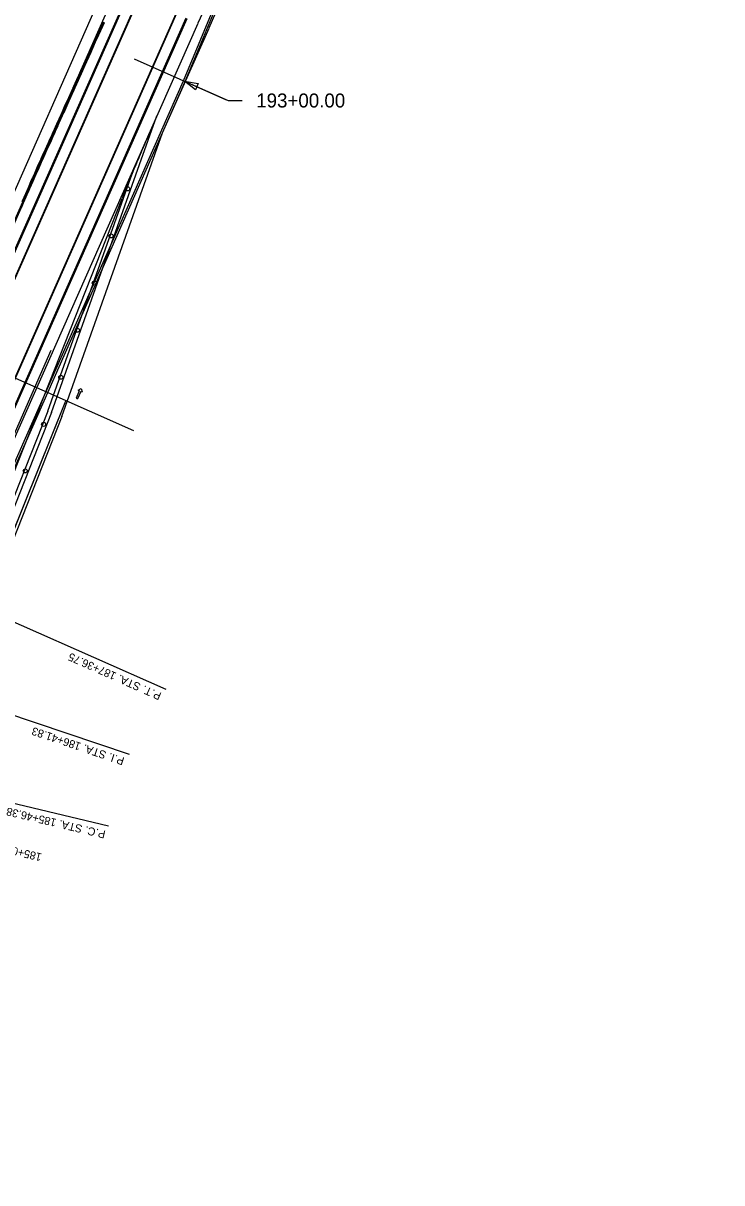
# Model space of a CAD drawing. Extents: x 659657 to 668193, y 633084 to 648639.
# Drawn here: x 662768 to 663466, y 643023 to 644182 of the extents above; entities that cross this region are included whole.
import ezdxf

# ---------------------------------------------------------------- set-up
doc = ezdxf.new("R2010")
doc.units = 0
for name, color, linetype in [('R_Border Prem', 7, 'Continuous'), ('R_MOT_Stage 1A_Striping', 7, 'Continuous'), ('R_MOT_Stage 1B', 7, 'Continuous'), ('R_MOT_Stage 1B_Striping', 7, 'Continuous'), ('R_MOT_Stage 1C', 7, 'Continuous'), ('R_MOT_Stage 1C_Striping', 7, 'Continuous'), ('R_MOT_Stage 1C_Striping_PPM', 7, 'Continuous'), ('R_MOT_Stage 2', 7, 'Continuous'), ('R_MOT_Stage 2_Striping', 7, 'Continuous'), ('R_MOT_Stage 2_Striping_PPM', 7, 'Continuous'), ('R_MOT_Stage 3', 7, 'Continuous'), ('R_MOT_Stage 3_Striping', 7, 'Continuous'), ('R_MOT_Stage 3_Striping_PPM', 7, 'Continuous'), ('R_MOT_Stage 4_Striping', 7, 'Continuous'), ('R_MOT_Stage 4_Striping_PPM', 7, 'Continuous'), ('R_MOT_Stage 5_Striping_PPM', 7, 'Continuous'), ('T_SIGNAL CONTROL CABINET', 7, 'Continuous')]:
    doc.layers.add(name, color=color, linetype=linetype)

msp = doc.modelspace()

# ---------------------------------------------------------------- linework, layer by layer
at = {"layer": 'R_Border Prem'}
msp.add_line((661686.8, 641562.9), (662861.9, 644217.7), dxfattribs=at)
at = {"layer": 'R_MOT_Stage 1A_Striping'}
for points in [[(662693, 643612.5), (662910.2, 643516.4)], [(662654.4, 643525.2), (662873.4, 643451.4)], [(662632.3, 643432.4), (662852.8, 643379.8)]]:
    msp.add_lwpolyline(points, dxfattribs=at)
at = {"layer": 'R_MOT_Stage 1B'}
for p, q in [((662927.9, 644124.5), (663042.2, 644399.9)), ((662929.7, 644123.8), (663044, 644399.2)), ((662731.8, 643681.5), (662927.9, 644124.5)), ((662733.6, 643680.7), (662929.7, 644123.7))]:
    msp.add_line(p, q, dxfattribs=at)
at = {"layer": 'R_MOT_Stage 1B_Striping'}
for p, q in [((662927.9, 644124.5), (663042.2, 644399.9)), ((662653.9, 643589.7), (662920.4, 644191.8)), ((662664, 643585.2), (662930.5, 644187.3)), ((662731.8, 643681.5), (662927.9, 644124.5)), ((662675.3, 643583.6), (662795.5, 643855.1))]:
    msp.add_line(p, q, dxfattribs=at)
for points in [[(662693, 643612.5), (662910.2, 643516.4)], [(662654.4, 643525.2), (662873.4, 643451.4)], [(662632.3, 643432.4), (662852.8, 643379.8)]]:
    msp.add_lwpolyline(points, dxfattribs=at)
at = {"layer": 'R_MOT_Stage 1C'}
for centre in [(662872.2, 644016.5), (662855.5, 643969.4), (662838.7, 643922.3), (662821.9, 643875.2), (662805.2, 643828.1), (662788, 643781.1), (662769.6, 643734.6)]:
    msp.add_circle(centre, 2, dxfattribs=at)
at = {"layer": 'R_MOT_Stage 1C_Striping'}
for p, q in [((662884, 644040.7), (662901.3, 644089.3)), ((662795.9, 643793), (662884, 644040.7)), ((662795.9, 643793), (662675.6, 643489.1))]:
    msp.add_line(p, q, dxfattribs=at)
at = {"layer": 'R_MOT_Stage 1C_Striping_PPM'}
for p, q in [((662883.3, 644106.6), (662920.9, 644191.6)), ((662893.8, 644101.9), (662931.4, 644186.9)), ((662896.1, 644077.4), (662942.4, 644182)), ((662907, 644072.6), (662953.4, 644177.2)), ((662859, 644051.7), (662883.3, 644106.6)), ((662869.5, 644047.1), (662893.8, 644101.9)), ((662716.3, 643671.4), (662896.1, 644077.4)), ((662806.2, 643789.1), (662907, 644072.6)), ((662694.8, 643680.9), (662859, 644051.7)), ((662705.4, 643676.2), (662869.5, 644047.1)), ((662806.2, 643789.1), (662685.9, 643485.2))]:
    msp.add_line(p, q, dxfattribs=at)
for radius in [5685.6, 5673.6]:
    msp.add_arc((668141.4, 641880.7), radius, 145.4889, 156.1234, dxfattribs=at)
at = {"layer": 'R_MOT_Stage 2'}
for centre in [(662872.2, 644016.5), (662855.5, 643969.4), (662838.7, 643922.3), (662821.9, 643875.2), (662805.2, 643828.1), (662788, 643781.1), (662769.6, 643734.6)]:
    msp.add_circle(centre, 2, dxfattribs=at)
at = {"layer": 'R_MOT_Stage 2_Striping'}
for p, q in [((662884, 644040.7), (662901.3, 644089.3)), ((662795.9, 643793), (662884, 644040.7)), ((662795.9, 643793), (662675.6, 643489.1))]:
    msp.add_line(p, q, dxfattribs=at)
at = {"layer": 'R_MOT_Stage 2_Striping_PPM'}
for p, q in [((662920.9, 644191.6), (662694.8, 643680.9)), ((662705.4, 643676.2), (662931.4, 644186.9)), ((662896.1, 644077.4), (662942.4, 644182)), ((662907, 644072.6), (662953.4, 644177.2)), ((662716.3, 643671.4), (662896.1, 644077.4)), ((662806.2, 643789.1), (662907, 644072.6)), ((662806.2, 643789.1), (662685.9, 643485.2))]:
    msp.add_line(p, q, dxfattribs=at)
for radius in [5685.6, 5673.6]:
    msp.add_arc((668141.4, 641880.7), radius, 145.4889, 156.1234, dxfattribs=at)
at = {"layer": 'R_MOT_Stage 3'}
for points in [[(662765.8, 643997.5), (662768, 644002.6), (662771.6, 644010.7), (662772.9, 644013.6), (662774.3, 644016.8), (662777.6, 644024.2), (662778.6, 644026.6), (662778.9, 644027.2), (662780, 644029.7), (662780.6, 644031.1), (662783.5, 644037.6), (662787, 644045.4), (662787.1, 644045.8), (662789.5, 644051), (662791.3, 644055.1), (662793.6, 644060.2), (662794.4, 644061.8), (662795.8, 644064.9), (662797.2, 644068.1), (662799.1, 644072.2), (662800.3, 644075), (662802.1, 644078.9), (662802.5, 644079.7), (662802.7, 644080.3), (662807, 644089.7), (662808.2, 644092.5), (662808.4, 644092.8), (662810.5, 644097.6), (662813.6, 644104.5), (662813.7, 644104.7), (662814.6, 644106.8), (662818.6, 644115.6), (662819.2, 644116.9), (662819.6, 644117.8), (662819.7, 644118.1), (662824, 644127.7), (662825.2, 644130.3), (662825.8, 644131.7), (662826.6, 644133.5), (662831.2, 644143.7), (662833.4, 644148.7), (662833.4, 644148.7), (662834.4, 644150.9), (662837.2, 644157.1), (662840, 644163.4), (662841, 644165.7), (662842.1, 644168.2), (662843.2, 644170.5), (662843.4, 644171), (662848.8, 644182.9)], [(662847, 644183.7), (662841.6, 644171.8), (662841.4, 644171.3), (662840.3, 644169), (662839.2, 644166.5), (662838.2, 644164.2), (662835.4, 644157.9), (662832.6, 644151.7), (662831.6, 644149.5), (662831.6, 644149.5), (662829.4, 644144.5), (662824.8, 644134.3), (662824, 644132.5), (662823.4, 644131.1), (662822.2, 644128.5), (662817.9, 644118.9), (662817.8, 644118.6), (662817.3, 644117.7), (662816.8, 644116.4), (662812.8, 644107.6), (662811.9, 644105.5), (662811.8, 644105.4), (662808.7, 644098.5), (662806.5, 644093.6), (662806.4, 644093.3), (662805.1, 644090.6), (662800.9, 644081.1), (662800.6, 644080.5), (662800.2, 644079.7), (662798.5, 644075.8), (662797.2, 644073), (662795.4, 644068.9), (662794, 644065.8), (662792.5, 644062.6), (662791.8, 644061), (662789.5, 644055.9), (662787.7, 644051.8), (662785.3, 644046.6), (662785.1, 644046.2), (662781.7, 644038.4), (662778.8, 644031.9), (662778.2, 644030.5), (662777.1, 644028), (662776.8, 644027.4), (662775.7, 644025), (662772.5, 644017.6), (662771.1, 644014.4), (662769.8, 644011.5), (662766.2, 644003.4)]]:
    msp.add_lwpolyline(points, dxfattribs=at)
at = {"layer": 'R_MOT_Stage 3_Striping'}
for p, q in [((662566.8, 643518.9), (662873.8, 644212.4)), ((662566.8, 643518.9), (662873.8, 644212.4)), ((662576.9, 643514.4), (662883.9, 644208)), ((662576.9, 643514.4), (662883.9, 644208)), ((662792.1, 643794.4), (662876.9, 644032.5)), ((662792.1, 643794.4), (662622.7, 643366.2))]:
    msp.add_line(p, q, dxfattribs=at)
msp.add_lwpolyline([(662664.5, 643771.8), (662673, 643789.3), (662681.2, 643807.2), (662686.7, 643819.5), (662692.2, 643831.8), (662703.2, 643856.3), (662714.5, 643881.9), (662720.2, 643894.8), (662725.9, 643907.6), (662736.5, 643931.3), (662742.3, 643944.5), (662748.1, 643957.7), (662754.9, 643973), (662761.7, 643988.3), (662787, 644045.4), (662800.3, 644075), (662807, 644089.7), (662813.6, 644104.5), (662825.8, 644131.7), (662841, 644165.7), (662848.8, 644183.1)], dxfattribs=at)
msp.add_arc((664648, 643302), 1915.9, 156.1234, 157.5861, dxfattribs=at)
at = {"layer": 'R_MOT_Stage 3_Striping_PPM'}
for p, q in [((662920.9, 644191.6), (662694.8, 643680.9)), ((662705.4, 643676.2), (662931.4, 644186.9)), ((662896.1, 644077.4), (662942.4, 644182)), ((662907, 644072.6), (662953.4, 644177.2)), ((662716.3, 643671.4), (662896.1, 644077.4)), ((662806.2, 643789.1), (662907, 644072.6)), ((662806.2, 643789.1), (662685.9, 643485.2))]:
    msp.add_line(p, q, dxfattribs=at)
for radius in [5685.6, 5673.6]:
    msp.add_arc((668141.4, 641880.7), radius, 145.4889, 156.1234, dxfattribs=at)
at = {"layer": 'R_MOT_Stage 4_Striping'}
for q in [(662876.9, 644032.5), (662622.7, 643366.2)]:
    msp.add_line((662792.1, 643794.4), q, dxfattribs=at)
at = {"layer": 'R_MOT_Stage 4_Striping_PPM'}
for p, q in [((662703.1, 643888.6), (662850.9, 644222.5)), ((662716.8, 643889.9), (662861.9, 644217.7)), ((662727.8, 643885), (662872.9, 644212.8)), ((662738.3, 643880.4), (662883.4, 644208.2)), ((662920.9, 644191.6), (662694.8, 643680.9)), ((662705.4, 643676.2), (662931.4, 644186.9)), ((662896.1, 644077.4), (662942.4, 644182)), ((662907, 644072.6), (662953.4, 644177.2)), ((662716.3, 643671.4), (662896.1, 644077.4)), ((662806.2, 643789.1), (662907, 644072.6)), ((662806.2, 643789.1), (662685.9, 643485.2))]:
    msp.add_line(p, q, dxfattribs=at)
msp.add_arc((668141.4, 641880.7), 5673.6, 145.4889, 156.1234, dxfattribs=at)
at = {"layer": 'R_MOT_Stage 5_Striping_PPM'}
for p, q in [((662703.1, 643888.6), (662850.9, 644222.5)), ((662716.8, 643889.9), (662861.9, 644217.7)), ((662727.8, 643885), (662872.9, 644212.8)), ((662738.3, 643880.4), (662883.4, 644208.2)), ((662920.9, 644191.6), (662694.8, 643680.9)), ((662705.4, 643676.2), (662931.4, 644186.9)), ((662896.1, 644077.4), (662942.4, 644182)), ((662907, 644072.6), (662953.4, 644177.2)), ((662716.3, 643671.4), (662896.1, 644077.4)), ((662806.2, 643789.1), (662907, 644072.6)), ((662572.6, 643263.9), (662866.5, 644006.8)), ((662572.6, 643263.9), (662866.5, 644006.8)), ((662572.6, 643263.9), (662866.5, 644006.8)), ((662806.2, 643789.1), (662685.9, 643485.2))]:
    msp.add_line(p, q, dxfattribs=at)
for centre, radius, start, end in [((668141.4, 641880.7), 5673.6, 145.4889, 156.1234), ((664648, 643302), 1915.9, 156.1234, 157.9178), ((664648, 643302), 1915.9, 157.9178, 158.4151)]:
    msp.add_arc(centre, radius, start, end, dxfattribs=at)
at = {"layer": 'T_SIGNAL CONTROL CABINET'}
for p, q in [((662878.5, 644146.4), (662969.9, 644105.9)), ((662740.9, 643835.5), (662878, 643774.8)), ((662823.7, 643814.7), (662820.4, 643807.2)), ((662825.2, 643814), (662821.9, 643806.5)), ((662822.4, 643815.3), (662825.7, 643817.1)), ((662822.4, 643815.3), (662823.7, 643814.7)), ((662825.2, 643814), (662826.5, 643813.5)), ((662825.7, 643817.1), (662826.5, 643813.5)), ((662619.4, 643331.4), (662810.3, 643804.6)), ((662619.5, 643331.5), (662810.3, 643804.6)), ((662820.4, 643807.2), (662821.9, 643806.5))]:
    msp.add_line(p, q, dxfattribs=at)
for points in [[(662767.1, 644003), (662770.7, 644011.1), (662772, 644014), (662773.4, 644017.2), (662776.7, 644024.6), (662777.7, 644027), (662778, 644027.6), (662779.1, 644030.1), (662779.7, 644031.5), (662782.6, 644038), (662786.1, 644045.8), (662786.2, 644046.2), (662788.6, 644051.4), (662790.4, 644055.5), (662792.7, 644060.6), (662793.5, 644062.2), (662794.9, 644065.4), (662796.3, 644068.5), (662798.1, 644072.6), (662799.4, 644075.4), (662801.2, 644079.3), (662801.5, 644080.1), (662801.8, 644080.7), (662806.1, 644090.2), (662807.3, 644092.9), (662807.4, 644093.2), (662809.6, 644098.1), (662812.7, 644104.9), (662812.8, 644105.1), (662813.7, 644107.2), (662817.7, 644116), (662818.3, 644117.3), (662818.7, 644118.2), (662818.8, 644118.5), (662823.1, 644128.1), (662824.3, 644130.7), (662824.9, 644132.1), (662825.7, 644133.9), (662830.3, 644144.1), (662832.5, 644149.1), (662832.5, 644149.1), (662833.5, 644151.3), (662836.3, 644157.5), (662839.1, 644163.8), (662840.1, 644166.1), (662841.2, 644168.6), (662842.3, 644170.9), (662842.5, 644171.4), (662847.9, 644183.3)], [(662928.8, 644124.1), (662972.6, 644104.8), (662986.6, 644104.8)]]:
    msp.add_lwpolyline(points, dxfattribs=at)
msp.add_lwpolyline([(662928.8, 644124.1), (662942.6, 644121.8), (662939.8, 644115.6)], close=True, dxfattribs=at)

# ---------------------------------------------------------------- texts
at = {"layer": 'R_MOT_Stage 1A_Striping'}
for s, rotation, p in [('P.T. STA. 187+36.75', 156.1234, (662906.5, 643512.5)), ('P.I. STA. 186+41.83', 161.3585, (662869.4, 643447.8)), ('P.C. STA. 185+46.38', 166.5936, (662850.5, 643374.8)), ('185+00', 166.5936, (662786.7, 643352))]:
    msp.add_text(s, height=8, rotation=rotation, dxfattribs=at).set_placement(p)
at = {"layer": 'R_MOT_Stage 1B_Striping'}
for s, rotation, p in [('P.T. STA. 187+36.75', 156.1234, (662906.5, 643512.5)), ('P.I. STA. 186+41.83', 161.3585, (662869.4, 643447.8)), ('P.C. STA. 185+46.38', 166.5936, (662850.5, 643374.8)), ('185+00', 166.5936, (662786.7, 643352))]:
    msp.add_text(s, height=8, rotation=rotation, dxfattribs=at).set_placement(p)
at = {"layer": 'T_SIGNAL CONTROL CABINET'}
msp.add_text('193+00.00', height=14, dxfattribs=at).set_placement((663000.6, 644097.8))

doc.saveas('drawing.dxf')
